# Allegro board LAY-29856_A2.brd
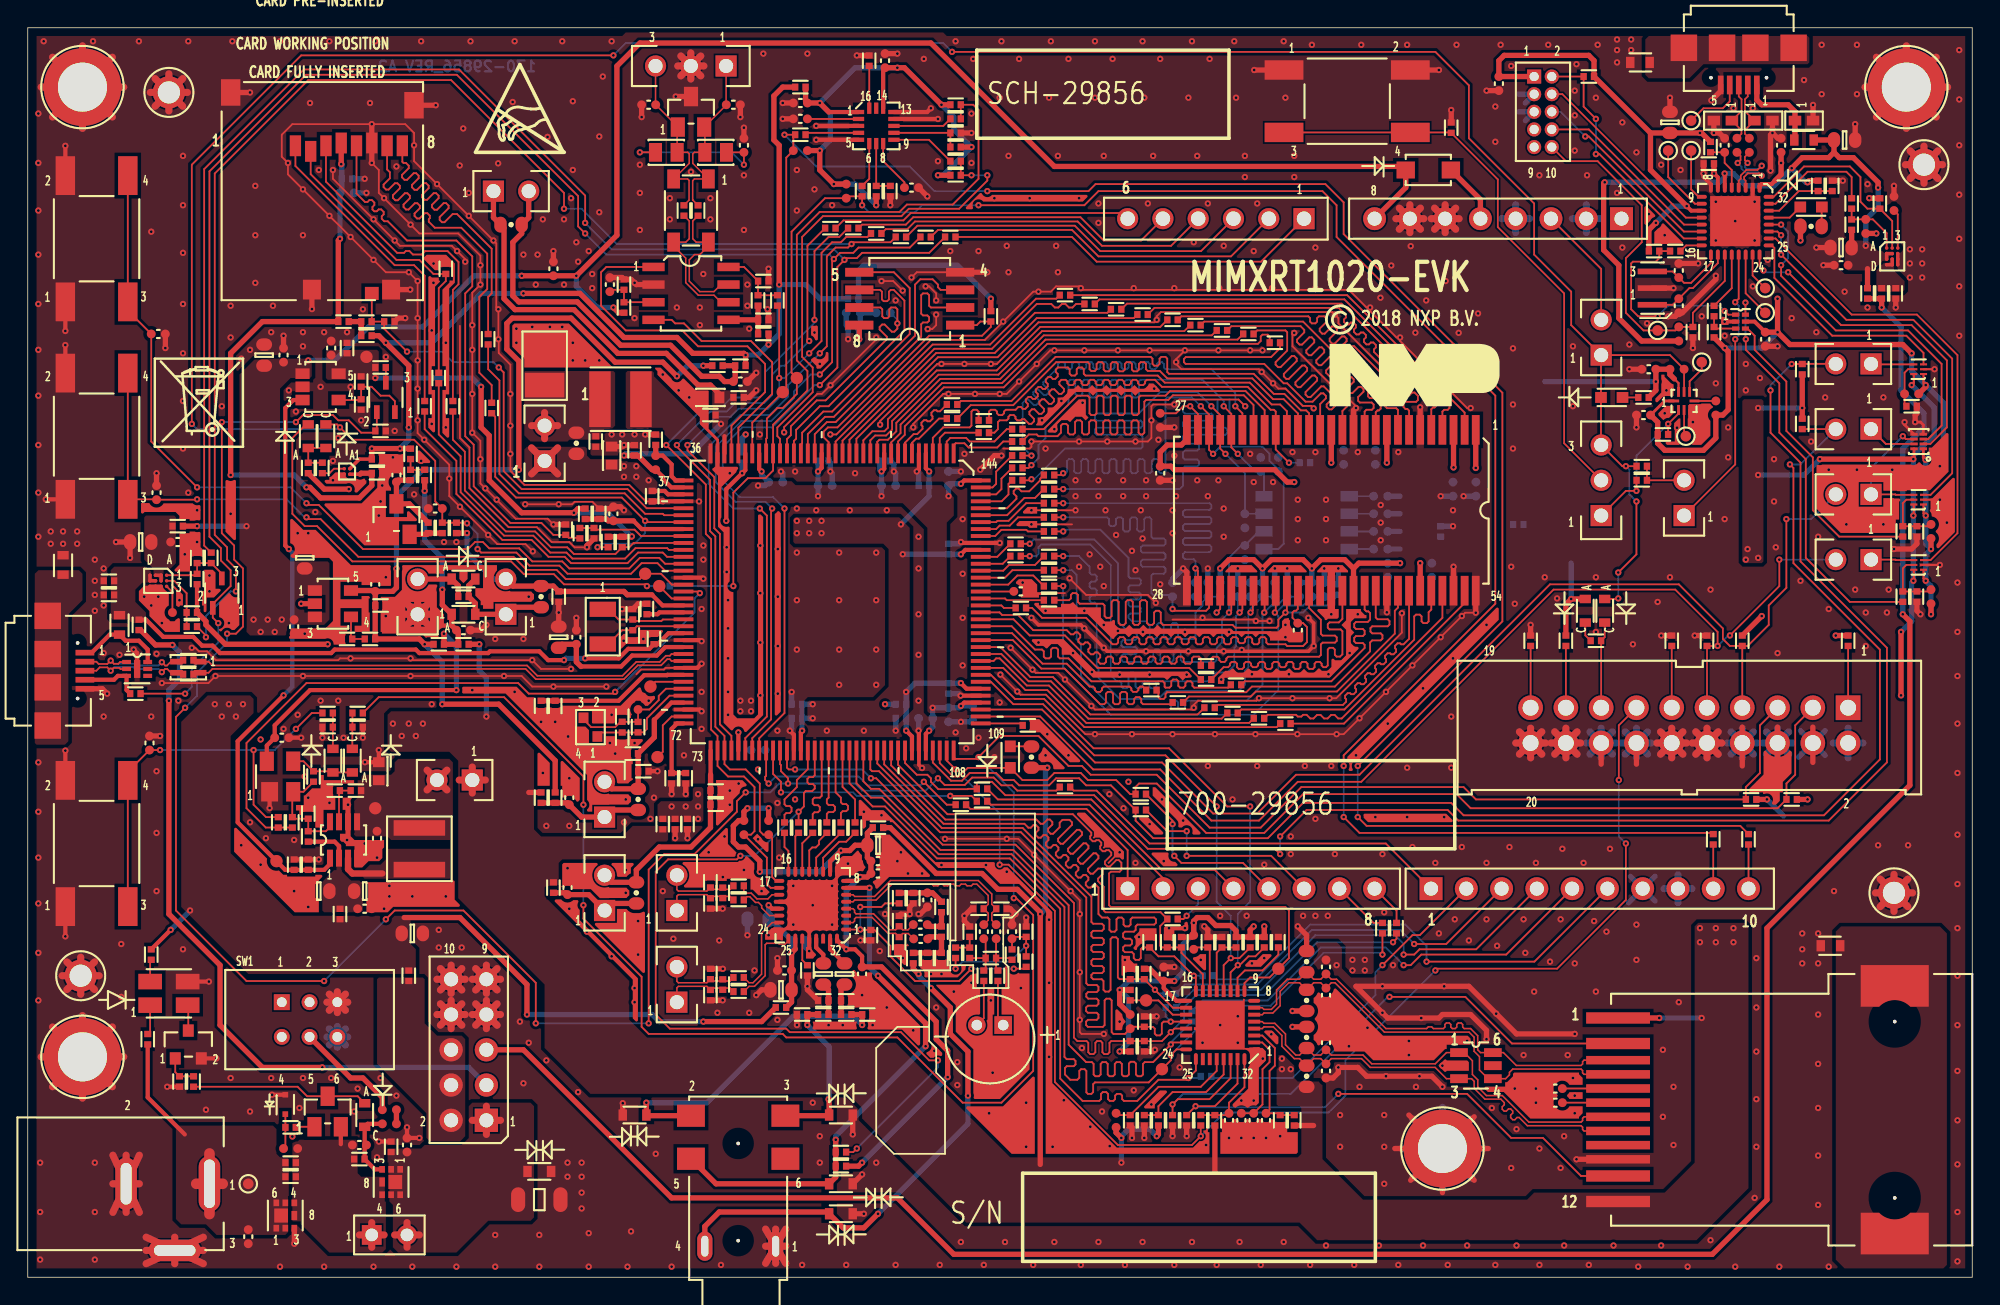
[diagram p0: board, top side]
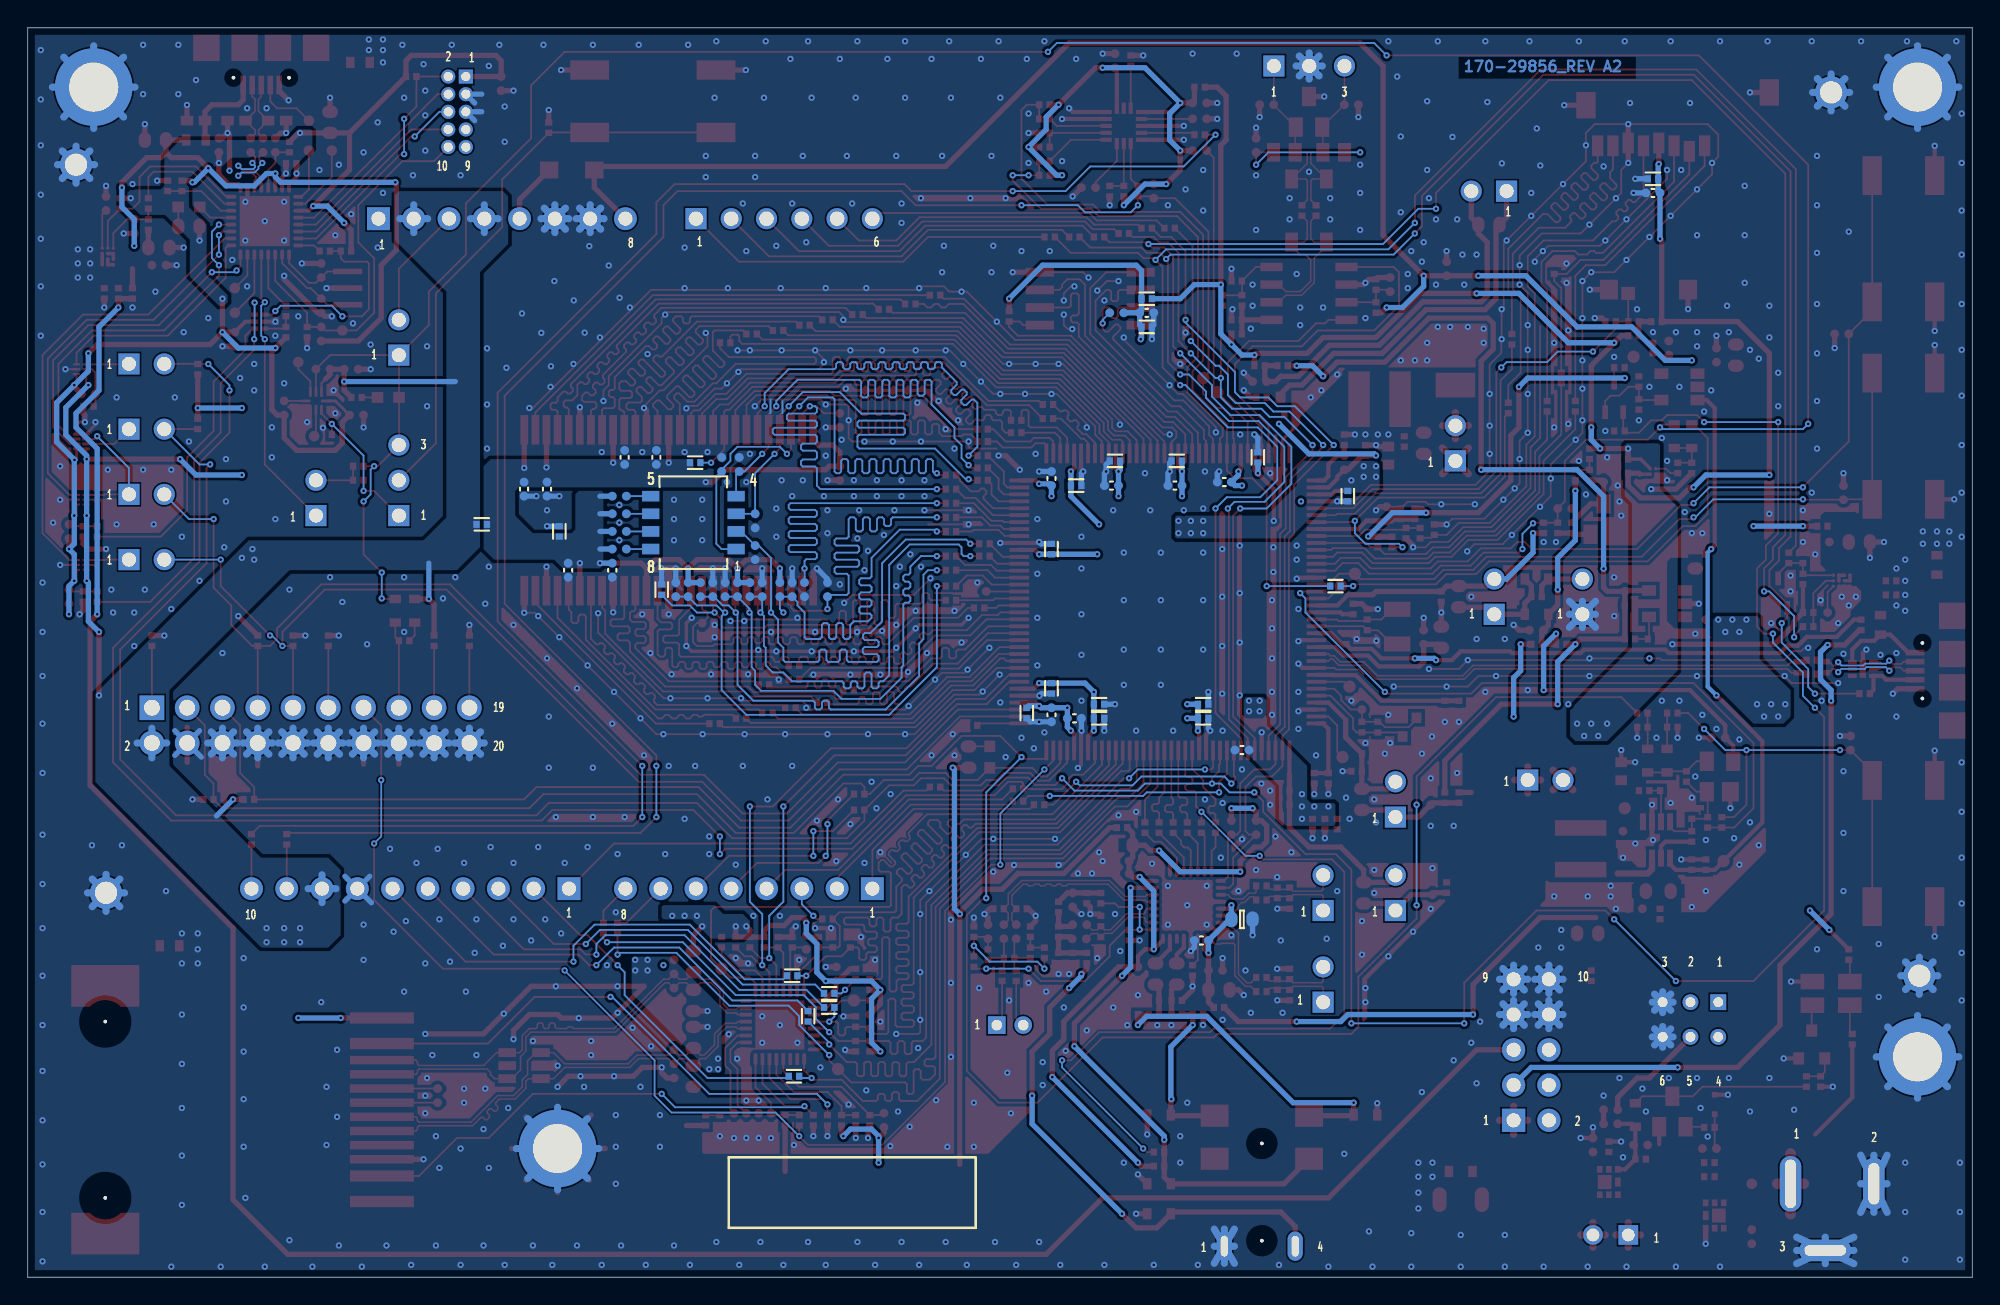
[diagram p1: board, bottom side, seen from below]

Outline 140 x 90 mm; copper layers: TOP, BOTTOM. Coordinates in mm from the lower left corner of the outline.
Outline path: 0,90 140,90 140,0 0,0 0,90

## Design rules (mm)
net group AUD_INT: nets AUD_INT N99827729
net group CAN1_H: nets CAN1_H N101254622
net group CAN1_L: nets CAN1_L N101254624
net group DP_SDA_USB_D: nets SDA_USB_DN SDA_USB_DP
net group ENET_RST: nets ENET_RST N101050998
net group ENET_RX: nets ENET_RXM ENET_RXP
net group ENET_TX: nets ENET_TXM ENET_TXP
net group GPIO_AD_B0_07: nets GPIO_AD_B0_07 N101505087
net group GPIO_AD_B1_08: nets GPIO_AD_B1_08 N101505089
net group GPIO_AD_B1_09: nets GPIO_AD_B1_09 N101505091
net group GPIO_AD_B1_11: nets GPIO_AD_B1_11 N100784828
net group GPIO_EMC_16: nets GPIO_EMC_16 SEMC_A0
net group GPIO_EMC_17: nets GPIO_EMC_17 SEMC_A1
net group GPIO_EMC_18: nets GPIO_EMC_18 SEMC_A2
net group GPIO_EMC_19: nets GPIO_EMC_19 SEMC_A3
net group GPIO_EMC_20: nets GPIO_EMC_20 SEMC_A4
net group GPIO_EMC_21: nets GPIO_EMC_21 SEMC_A5
net group GPIO_EMC_22: nets GPIO_EMC_22 SEMC_A6
net group GPIO_EMC_23: nets GPIO_EMC_23 SEMC_A7
net group GPIO_EMC_24: nets GPIO_EMC_24 SEMC_A8
net group GPIO_EMC_25: nets GPIO_EMC_25 SEMC_A9
net group GPIO_EMC_26: nets GPIO_EMC_26 SEMC_A11
net group GPIO_EMC_27: nets GPIO_EMC_27 SEMC_A12
net group HP_MIC1: nets HP_MIC1N HP_MIC1P
net group MAIN_MIC2: nets MAIN_MIC2N MAIN_MIC2P
net group N99903738: nets N99903738 N99904961
net group OTG1_DN: nets N99833038 OTG1_DN
net group OTG1_DP: nets N99833040 OTG1_DP
net group SAI1_MCLK: nets N99827829 SAI1_MCLK
net group SAI1_RXD: nets N99827789 SAI1_RXD
net group SAI1_TX_BCLK: nets N99827769 SAI1_TX_BCLK
net group SAI1_TX_SYNC: nets N99827749 SAI1_TX_SYNC
net group SAI1_TXD: nets N99827809 SAI1_TXD
net group SD1_CLK: nets N100763759 SD1_CLK
net group SD1_CMD: nets N100585038 SD1_CMD
net group SD1_D0: nets N100585007 SD1_D0
net group SD1_D1: nets N100585009 SD1_D1
net group SD1_D2: nets N100585016 SD1_D2
net group SD1_D3: nets N100585089 SD1_D3
net group SDA_USB: nets SDA_USB_CONN_DN SDA_USB_CONN_DP
net group SEMC_A10: nets N101509422 SEMC_A10
net group SEMC_BA0: nets N101509590 SEMC_BA0
net group SEMC_BA1: nets N101509597 SEMC_BA1
net group SEMC_CAS: nets N101510168 SEMC_CAS
net group SEMC_CKE: nets N101509855 SEMC_CKE
net group SEMC_CLK: nets N101219622 SEMC_CLK
net group SEMC_CS0: nets N101511316 SEMC_CS0
net group SEMC_D0: nets N101507443 SEMC_D0
net group SEMC_D1: nets N101507450 SEMC_D1
net group SEMC_D2: nets N101507457 SEMC_D2
net group SEMC_D3: nets N101507470 SEMC_D3
net group SEMC_D4: nets N101507472 SEMC_D4
net group SEMC_D5: nets N101507474 SEMC_D5
net group SEMC_D6: nets N101507491 SEMC_D6
net group SEMC_D7: nets N101507493 SEMC_D7
net group SEMC_D8: nets N101507495 SEMC_D8
net group SEMC_D9: nets N101507512 SEMC_D9
net group SEMC_D10: nets N101507514 SEMC_D10
net group SEMC_D11: nets N101507516 SEMC_D11
net group SEMC_D12: nets N101507533 SEMC_D12
net group SEMC_D13: nets N101507535 SEMC_D13
net group SEMC_D14: nets N101507537 SEMC_D14
net group SEMC_D15: nets N101507548 SEMC_D15
net group SEMC_DM0: nets N101509859 SEMC_DM0
net group SEMC_DM1: nets N101509857 SEMC_DM1
net group SEMC_RAS: nets N101509861 SEMC_RAS
net group SEMC_WE: nets N101509863 SEMC_WE
net group SPK_LN: nets N99828318 SPK_LN
net group SPK_LP: nets N99828322 SPK_LP
net group SPK_RN: nets N99827958 SPK_RN
net group SPK_RP: nets N99827962 SPK_RP
net group 3W: nets JTAG_DACK JTAG_NSRST JTAG_RTCK JTAG_TCK N99881896 SDA_JTAG_TCLK SDA_RST SDA_RST_LED SDA_RST_TGTMCU_B SDA_RST_TGTMCU_J_B SDA_SPI0_RST_B SDA_SPI0_SCK SW1_RST_B SWD_CLK_TGTMCU_BUF
net group ENET_RXD1: nets N101505079
net group GPIO_AD_B1_10: nets GPIO_AD_B1_10 N100784802 N101140611
net group POWER: nets 5V_USB_OTG CAN_VIO_3V3 DCDC_3V3_PG FLASH_3V3 HP_JD MCU_DCDC_IN N99781517 N99781633 N99781637 N99833017 N99833020 N99903207 N99903209 N99903219 N99903223 N99904959 N99904975 N99916957 N100054253 N100054299 P5V0_SDA_USB_CONN_VBUS P5V_SDA_S SENSOR_3V3 VAUD_3V3 VDD_COIN_3V VDD_HIGH_IN_3V3 VDD_HIGH_IN_MCU VDD_SNVS_3V3 VDD_SNVS_IN VDD_USB_3V VDDA_ADC_3P3_MCU VDDA_ADC_3V3 VLDO_3V3 VSD_3V3
net group SD1: nets SD_CD_SW

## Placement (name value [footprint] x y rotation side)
C1  0.1UF  [CC0402_25]  27.3 9.53 90 top
C2  1.0UF  [0402_CC]  26.16 9.4 90 top
C3  47uF  [CC1206_OV]  36.83 5.59 0 top
C4  0.1UF  [CC0402_25]  15.88 2.92 270 top
C5  0.01UF  [CC0402_25]  23.88 9.53 0 top
C6  1.0UF  [0402_CC]  49.53 35.05 0 top
C7  0.22uF  [0402_CC]  49.53 34.04 0 top
C8  0.22uF  [0402_CC]  64.52 57.02 180 bottom
C9  0.22uF  [0402_CC]  66.29 52.45 90 bottom
C10  0.22uF  [0402_CC]  51.44 59.05 90 bottom
C11  0.22uF  [0402_CC]  44.96 56.26 270 bottom
C12  0.22uF  [0402_CC]  66.29 42.42 270 bottom
C13  0.22uF  [0402_CC]  62.87 40.26 180 bottom
C14  0.22uF  [0402_CC]  62.87 41.27 180 bottom
C15  0.22uF  [0402_CC]  55.37 40.26 180 bottom
C16  0.22uF  [0402_CC]  55.37 41.27 180 bottom
C17  4.7uF  [0402_CC]  44.96 56.26 270 top
C18  22UF  [0603_CC]  42.04 59.18 90 top
C19  4.7uF  [0402_CC]  44.32 36.45 0 top
C20  0.22uF  [0402_CC]  43.56 37.72 180 top
C21  4.7uF  [0402_CC]  37.97 41.15 270 top
C22  0.22uF  [0402_CC]  36.96 41.15 270 top
C23  0.22uF  [0402_CC]  38.23 49.02 270 top
C24  0.22uF  [0402_CC]  44.58 48.13 90 top
C25  0.22uF  [0402_CC]  47.37 35.94 270 top
C26  4.7uF  [0402_CC]  46.35 35.94 270 top
C28  0.1UF  [CC0402_25]  29.34 55.37 180 top
C29  0.1UF  [CC0402_25]  26.54 57.78 90 top
C30  1.0UF  [0402_CC]  25.15 57.91 0 top
C31  22UF  [0603_CC]  49.15 63.37 180 top
C32  4.7uF  [0402_CC]  51.18 63.37 0 top
C33  0.22uF  [0402_CC]  49.15 62.1 180 top
C35  0.22uF  [0402_CC]  43.69 59.56 90 top
C36  4.7PF  [0402_CC]  42.8 40.39 90 top
C37  4.7PF  [0402_CC]  42.8 38.86 270 top
C38  33UF  [CC1210]  37.21 65.66 90 top
C39  0.22uF  [0402_CC]  40.89 60.2 270 top
C40  10uF  [CC0603_OV]  19.94 51.82 90 top
C41  0.1UF  [CC0402_25]  19.18 46.86 270 top
C42  4.7uF  [0402_CC]  25.4 48.39 0 top
C43  0.1UF  [CC0402_25]  25.02 49.91 90 top
C44  18PF  [0402_CC]  43.56 47.75 90 top
C45  18PF  [0402_CC]  43.56 46.23 270 top
C46  0.22uF  [0402_CC]  45.21 60.33 90 top
C47  0.1UF  [CC0402_25]  38.86 28.07 90 top
C48  0.1UF  [CC0402_25]  31.37 46.61 0 top
C49  10uF  [CC0603_OV]  20.95 27.81 180 top
C50  10uF  [CC0603_OV]  24.26 27.81 0 top
C51  0.1UF  [CC0402_25]  24.26 26.54 0 top
C52  22UF  [0603_CC]  25.27 36.45 90 top
C53  0.1UF  [CC0402_25]  25.15 31.62 270 top
C54  0.22uF  [0402_CC]  20.19 33.4 90 top
C55  0.1UF  [CC0402_25]  51.31 64.52 0 top
C56  0.1UF  [CC0402_25]  38.99 34.54 90 top
C57  1000pF  [0402_CC]  20.19 29.72 90 top
C58  1000pF  [0402_CC]  19.18 29.72 90 top
C59  1000pF  [0402_CC]  21.59 39.62 180 top
C60  0.1UF  [CC0402_25]  18.29 38.86 0 top
C61  1.0UF  [0402_CC]  23.75 40.64 180 top
C62  10uF  [CC0603_OV]  17.02 66.42 90 top
C63  0.1UF  [CC0402_25]  18.41 66.42 90 top
C64  4.7uF  [0402_CC]  22.99 66.93 90 top
C65  0.1UF  [CC0402_25]  21.84 66.93 90 top
C66  4.7uF  [0402_CC]  47.5 32.64 270 top
C67  0.1UF  [CC0402_25]  64.64 40.26 180 bottom
C68  0.1UF  [CC0402_25]  52.58 37.97 0 bottom
C69  0.1UF  [CC0402_25]  57.4 57.02 0 bottom
C70  0.1UF  [CC0402_25]  66.29 57.53 90 bottom
C71  4.7uF  [0402_CC]  46.61 32.64 270 top
C72  0.1UF  [CC0402_25]  61.98 57.02 0 bottom
C73  0.1UF  [CC0402_25]  53.85 57.28 0 bottom
C74  0.1UF  [CC0402_25]  66.29 40.51 270 bottom
C75  0.1UF  [CC0402_25]  71.5 49.4 0 top
C76  4.7uF  [0402_CC]  41.15 54.99 90 top
C77  0.1UF  [CC0402_25]  42.16 54.99 90 top
C78  1.0UF  [0402_CC]  45.09 45.97 90 top
C79  10uF  [CC0603_OV]  38.23 46.1 90 top
C80  0.1UF  [CC0402_25]  39.5 46.1 90 top
C81  4.7uF  [0402_CC]  5.84 49.15 180 top
C82  10uF  [CC0603_OV]  8.13 52.96 180 top
C83  0.1UF  [CC0402_25]  10.79 52.96 0 top
C84  4.7uF  [0402_CC]  5.84 50.16 180 top
C85  0.1UF  [CC0402_25]  41.91 71.5 90 top
C86  1.0UF  [0402_CC]  42.93 71.5 90 top
C87  1.0UF  [0402_CC]  52.96 68.96 0 top
C88  56PF  [CC0402_25]  50.8 84.45 180 top
C89  0.01UF  [CC0402_25]  51.56 81.53 90 top
C90  56PF  [CC0402_25]  44.7 84.45 180 top
C91  10uF  [CC0603_OV]  61.21 31.11 0 top
C92  0.1UF  [CC0402_25]  61.21 29.08 0 top
C93  0.1UF  [CC0402_25]  60.07 21.84 270 top
C94  0.1UF  [CC0402_25]  61.21 29.97 0 top
C95  10uF  [CC0603_OV]  54.23 20.7 180 top
C96  0.1UF  [CC0402_25]  54.48 22.1 180 top
C97  0.1UF  [CC0402_25]  55.5 24.26 0 bottom
C98  4.7uF  [0402_CC]  60.71 24.64 270 top
C99  10uF  [CC0603_OV]  52.58 25.78 180 bottom
C100  4.7uF  [0402_CC]  56.13 22.1 270 top
C101  220PF  [0402_CC]  60.45 18.92 180 top
C102  22UF  [CC0603_OV]  58.8 21.84 270 top
C103  22UF  [CC0603_OV]  57.28 21.84 270 top
C104  220PF  [0402_CC]  55.75 18.92 180 top
C105  4.7uF  [0402_CC]  71.88 24.89 90 top
C106  0.1UF  [CC0402_25]  70.87 24.89 90 top
C107  15PF  [0402_CC]  70.1 26.54 180 top
C108  4.7uF  [0402_CC]  63.75 27.3 270 top
C109  0.1UF  [CC0402_25]  64.77 27.18 270 top
C110  15PF  [0402_CC]  62.74 25.65 270 top
C111  0.1UF  [CC0402_25]  69.72 24.89 90 top
C112  0.1UF  [CC0402_25]  64.26 25.4 0 top
C113  4.7uF  [0402_CC]  66.8 23.37 90 top
C114  0.1UF  [CC0402_25]  68.83 24.89 90 top
C115  0.1UF  [CC0402_25]  64.29 24.37 0 top
C116  15PF  [0402_CC]  62.74 24.13 270 top
C117  15PF  [0402_CC]  64.77 22.99 270 top
C118  15PF  [0402_CC]  65.79 22.99 270 top
C119  15PF  [0402_CC]  68.45 26.54 180 top
C120  15PF  [0402_CC]  49.15 28.45 270 top
C121  15PF  [0402_CC]  49.15 21.84 270 top
C122  15PF  [0402_CC]  50.04 27.69 270 top
C123  15PF  [0402_CC]  50.04 21.08 270 top
C124  15PF  [0402_CC]  49.15 26.92 270 top
C125  15PF  [0402_CC]  49.15 20.32 270 top
C126  4.7uF  [0402_CC]  90.17 11.3 270 top
C127  0.1UF  [CC0402_25]  89.15 11.3 270 top
C128  2.2uF  [CC0402_25]  87.38 11.3 270 top
C129  0.1UF  [CC0402_25]  88.27 11.3 270 top
C130  10PF  [CC0402_25]  93.47 22.35 90 top
C131  10PF  [CC0402_25]  93.47 20.32 270 top
C132  10PF  [CC0402_25]  93.47 16.89 90 top
C133  10PF  [CC0402_25]  93.47 14.86 270 top
C134  0.1UF  [CC0402_25]  81.79 21.84 90 top
C135  0.1UF  [CC0402_25]  109.98 12.57 180 top
C136  0.1UF  [CC0402_25]  109.98 13.59 180 top
C137  0.1UF  [CC0402_25]  86.49 11.3 270 top
C138  4.7uF  [0402_CC]  22.99 79.12 0 bottom
C139  0.1UF  [CC0402_25]  22.99 78.11 0 bottom
C140  18PF  [0402_CC]  40.77 53.59 270 top
C141  18PF  [0402_CC]  38.73 53.85 90 top
C142  1.0UF  [0402_CC]  59.44 68.45 180 bottom
C143  0.1UF  [CC0402_25]  59.44 69.47 180 bottom
C144  4.7uF  [0402_CC]  101.73 53.72 90 bottom
C145  0.1UF  [CC0402_25]  102.62 56.77 270 bottom
C146  0.1UF  [CC0402_25]  104.27 56.77 270 bottom
C147  0.1UF  [CC0402_25]  97.92 50.93 270 bottom
C148  0.1UF  [CC0402_25]  97.03 59.05 90 bottom
C149  0.1UF  [CC0402_25]  81.53 57.91 270 top
C150  0.1UF  [CC0402_25]  101.09 50.93 270 bottom
C151  0.1UF  [CC0402_25]  94.74 59.05 90 bottom
C152  0.1UF  [CC0402_25]  116.71 65.41 180 top
C153  0.1UF  [CC0402_25]  116.33 62.1 180 top
C154  0.1UF  [CC0402_25]  125.09 67.56 270 top
C155  10uF  [CC0603_OV]  118.24 83.19 90 top
C156  1.0UF  [0402_CC]  121.03 80.21 180 top
C157  0.1UF  [CC0402_25]  126.24 81.53 90 top
C158  1000pF  [0402_CC]  102.49 82.8 90 top
C159  10uF  [CC0603_OV]  130.81 81.92 0 top
C160  22PF  [CC0402_25]  118.87 69.98 270 top
C161  22PF  [CC0402_25]  118.87 72.52 90 top
C162  2.2uF  [CC0402_25]  122.17 81.53 90 top
C163  0.1UF  [CC0402_25]  105.92 85.98 270 top
C164  10uF  [CC0603_OV]  130.56 74.17 180 top
C165  0.1UF  [CC0402_25]  130.56 72.9 180 top
C166  4.7uF  [0402_CC]  134.49 70.87 270 top
C167  0.1UF  [CC0402_25]  61.72 87.63 90 top
C168  0.1UF  [CC0402_25]  55.63 84.58 180 top
C169  0.1UF  [CC0402_25]  63.63 78.49 0 top
C170  0.1UF  [CC0402_25]  55.63 83.44 180 top
C171  1.0UF  [0402_CC]  25.15 58.93 0 top
C172  0.1UF  [CC0402_25]  9.4 67.94 0 top
C173  0.1UF  [CC0402_25]  8.76 38.48 90 top
C174  0.1UF  [CC0402_25]  9.27 56.52 90 top
C175  10PF  [CC0402_25]  91.44 46.61 270 top
C176  4.7uF  [0402_CC]  68.07 40.64 270 bottom
C177  4.7uF  [0402_CC]  61.72 58.8 0 bottom
C178  4.7uF  [0402_CC]  57.28 58.8 0 bottom
C179  10uF  [CC0603_OV]  27.69 24.77 0 top
C180  0.1UF  [CC0402_25]  37.85 72.64 90 top
D1  MM5Z5V1ST1G  [SOD_523_1P4]  18.54 12.45 90 top
D2  RB521S30  [SOD523]  24.26 11.68 90 top
D3  LED_RED-GRN  [LED_DUAL_3025MM_SM]  10.16 20.45 0 top
D4  RB521S30  [SOD523]  31.37 47.75 180 top
D5  GREEN  [LED_0603]  70.74 37.47 270 top
D6  RB521S30  [SOD523]  31.37 50.29 180 top
D7  RB521S30  [SOD523]  20.19 60.58 270 top
D8  RB521S30  [SOD523]  21.46 60.58 270 top
D9  RB521S30  [SOD523]  21.97 37.21 270 top
D10  RB521S30  [SOD523]  23.37 37.21 270 top
D11  NUP2105L  [SOT-23]  47.75 83.95 0 top
D12  RB521S30  [SOD523]  112.14 48.01 90 top
D13  RB521S30  [SOD523]  113.54 48.01 90 top
D14  MBR120VLSFT1G  [SOD-123]  100.84 79.76 0 top
D15  RED  [LED_0603]  114.05 63.37 180 top
D16  GREEN  [LED_0603]  128.4 77.09 180 top
FL1  ACT45B-510-2P  [IND4_4P7X3P4_SMT]  47.75 76.83 270 top
H1  .635" LONG  [SPACER_139T]  3.94 85.72 0 top
H2  .635" LONG  [SPACER_139T]  135.25 85.72 0 top
H3  .635" LONG  [SPACER_139T]  3.94 15.88 0 top
H4  .635" LONG  [SPACER_139T]  101.85 9.27 270 top
J1  HDR 2X5  [HDR205]  33.02 11.3 180 top
J2  CON_1_PWR  [CON3_PWR_TH]  13.08 6.73 270 top
J3  HDR 1X2  [HDR102]  41.53 26.42 180 top
J4  HDR 1X2  [HDR102]  37.21 58.8 180 top
J5  HDR 1X2  [HDR102]  41.53 33.15 180 top
J6  HDR 1X2  [HDR102]  34.42 47.75 180 top
J7  HDR 1X2  [HDR102]  28.07 47.75 180 top
J8  HDR 1X2  [HDR102]  32 35.81 270 top
J9  USB_MICROAB_RECEPTACLE  [CON_USB5_MICROAB_0P65_SM]  1.47 43.69 270 top
J10  HDR_1X3  [HDR103]  50.28 87.25 270 top
J11  PJ31360-I  [CON6_AUDJACK_RA_TH]  53.85 2.24 90 top
J12  HDR 1X2  [HDR102]  46.74 26.42 180 top
J13  HDR 1X2  [HDR102]  46.74 19.81 180 top
J14  RJ45_YLW+GRN  [CON12_RJ45_1P02_SM]  124.46 12.06 270 top
J15  95220030-14RRF  [CON_SDCARD_95220]  21.21 78.23 0 top
J16  BH25420B301  [HDR_2X10M_100_TH]  131.06 41.02 270 top
J17  CON 1X8  [CON_SKT1X8_TH]  79.19 27.99 90 top
J18  CON 1X6  [CON_SKT1X6_TH]  91.89 76.25 270 top
J19  CON 1X10  [CON_SKT1X10_TH]  101.03 27.99 90 top
J20  CON 1X8  [CON_SKT1X8_TH]  114.75 76.25 270 top
J21  HDR 1X2  [HDR102]  113.28 66.42 180 top
J22  HDR_1X3  [HDR103]  113.28 54.86 180 top
J23  USB_MICROAB_RECEPTACLE  [CON_USB5_MICROAB_0P65_SM]  123.19 88.52 180 top
J24  HDR 1X2  [HDR102]  119.25 54.86 180 top
J25  HDR 1X2  [HDR102]  132.72 65.79 270 top
J26  HDR 1X2  [HDR102]  132.72 61.09 270 top
J27  HDR 1X2  [HDR102]  132.72 56.39 270 top
J28  HDR 1X2  [HDR102]  132.72 51.69 270 top
J29  HDR 2X5  [HDR205_50_TH]  108.46 86.49 270 top
J37  HDR 1X2  [HDR102]  33.53 78.23 90 top
JP1  SHORT_100mil  [100MIL_TH]  24.77 3.05 0 top
L1  4.7uH  [IND_VLS4012E]  42.67 63.25 0 top
L2  1uH  [IND_4020]  28.19 30.86 90 top
L3  330 OHM  [IND_1608]  6.6 46.99 90 top
L4  90OHM  [IND4_CHOKE_0805]  11.56 43.94 180 top
L5  330 OHM  [IND_1608]  2.54 51.31 90 top
L6  120 Ohm  [0402_CC]  58.93 18.92 0 top
L7  120 Ohm  [0402_CC]  57.28 18.92 180 top
L8  120 Ohm  [0402_CC]  63.75 22.99 270 top
L9  120 Ohm  [0402_CC]  91.19 11.3 90 top
L10  330 OHM  [IND_1608]  129.79 23.88 0 top
L11  330 OHM  [IND_1608]  127.89 81.92 0 top
L12  330 OHM  [IND_1608]  116.08 87.5 180 top
L13  120 Ohm  [0402_CC]  107.31 54.23 180 bottom
L20  120 Ohm  [0402_CC]  27.43 21.72 90 top
NOREF  -  []  4.36 39.91 90 top
NOREF#2  -  []  121.19 86.4 0 top
NOREF#3  -  []  14.13 70.56 90 top
NOREF#4  -  []  134.64 72.93 90 top
NOREF#5  -  []  1.44 39.74 90 top
NOREF#6  -  []  114.5 5.45 90 top
NOREF#7  -  []  8.56 49.48 0 top
NOREF#8  -  []  135.62 50.78 90 top
NOREF#9  -  []  119.45 62.5 90 top
NOREF#10  -  []  59.87 72.39 0 top
NOREF#11  -  []  138.11 80.14 0 top
NOREF#12  -  []  22.59 57.64 90 top
NOREF#13  -  []  26.16 71.14 90 top
NOREF#14  -  []  59.87 71.12 90 top
NOREF#15  -  []  22.59 57.64 0 top
NOREF#16  -  []  59.81 81.93 0 top
NOREF#17  -  []  8.8 49.76 0 top
NOREF#18  -  []  0 0 0 top
NOREF#19  -  []  118.85 62.47 0 top
NOREF#20  -  []  118.53 62.49 0 top
NOREF#21  -  []  8.56 49.48 90 top
NOREF#22  -  []  119.42 85.63 90 top
NOREF#23  -  []  22.57 81.7 90 top
NOREF#24  -  []  -0.57 11.33 90 top
NOREF#25  -  []  0 0 90 top
NOREF#26  -  []  121.89 85.88 0 top
NOREF#27  -  []  62.36 81.93 90 top
NOREF#28  -  []  121.89 85.88 0 top
NOREF#29  -  []  4.11 42.39 90 top
NOREF#30  -  []  10.58 1.93 0 top
NOREF#31  -  []  14.61 85.34 0 top
NOREF#32  -  []  -0.01 39.2 90 top
NOREF#33  -  []  22.79 57.84 0 top
NOREF#34  -  []  139.82 2.47 90 top
NOREF#35  -  []  -0.79 39.91 90 top
NOREF#36  -  []  135.79 65.76 0 top
NOREF#37  -  []  60.59 81.66 90 top
NOREF#38  -  []  108.2 38.48 90 top
NOREF#39  -  []  44.34 61.19 90 top
NOREF#40  -  []  20.46 71.14 90 top
NOREF#41  -  []  62.57 84.43 0 top
NOREF#42  -  []  108.46 86.49 0 top
NOREF#43  -  []  47.75 11.64 0 top
NOREF#44  -  []  47.8 12.84 0 top
NOREF#45  -  []  114.5 15.63 90 top
NOREF#46  -  []  9.14 59.82 0 top
NOREF#47  -  []  94.49 68.96 0 top
NOREF#48  -  []  47.91 38.64 90 top
NOREF#49  -  []  32.26 81.03 0 top
NOREF#50  -  []  82.04 30.86 0 top
NOREF#51  -  []  114.5 8.5 90 top
NOREF#52  -  []  114.04 24.47 0 top
NOREF#53  -  []  108.46 85.22 90 top
NOREF#54  -  []  3.59 41.69 90 top
NOREF#55  -  []  60.77 67.74 90 top
NOREF#56  -  []  41.01 38.95 90 top
NOREF#57  -  []  135.79 51.66 0 top
NOREF#58  -  []  7.08 6.73 90 top
NOREF#59  -  []  21.47 81.5 0 top
NOREF#60  -  []  135.62 55.48 90 top
NOREF#61  -  []  122.96 68.33 0 top
NOREF#62  -  []  5.4 21.72 0 top
NOREF#63  -  []  -0.79 39.91 0 top
NOREF#64  -  []  47.8 -0.01 90 top
NOREF#65  -  []  60.78 73.24 0 top
NOREF#66  -  []  119.65 62.47 90 top
NOREF#67  -  []  114.5 5.45 90 top
NOREF#68  -  []  14.13 70.56 0 top
NOREF#69  -  []  71.63 1.14 0 top
NOREF#70  -  []  59.87 72.39 0 top
NOREF#71  -  []  1.44 39.74 90 top
NOREF#72  -  []  41.36 38.57 90 top
NOREF#73  -  []  135.79 56.36 0 top
NOREF#74  -  []  119.24 88.55 0 top
NOREF#75  -  []  114.18 3.89 90 top
NOREF#76  -  []  47.91 38.64 0 top
NOREF#77  -  []  139.82 2.47 90 top
NOREF#78  -  []  133.84 72.93 0 top
NOREF#79  -  []  20.46 71.14 90 top
NOREF#80  -  []  110.74 41.02 0 top
NOREF#81  -  []  134.42 3.15 90 top
NOREF#82  -  []  40.62 61.58 0 top
NOREF#83  -  []  114.5 5.45 90 top
NOREF#84  -  []  114.5 7.29 90 top
NOREF#85  -  []  51.15 2.64 90 top
NOREF#86  -  []  135.62 51.83 0 top
NOREF#87  -  []  47.8 -0.01 0 top
NOREF#88  -  []  20.46 71.14 90 top
NOREF#89  -  []  93.73 62.74 0 top
NOREF#90  -  []  59.87 68.58 90 top
NOREF#91  -  []  14.61 85.34 0 top
NOREF#92  -  []  4.11 42.39 90 top
NOREF#93  -  []  49.16 37.94 90 top
NOREF#94  -  []  8.8 49.76 0 top
NOREF#95  -  []  60.59 81.66 0 top
NOREF#96  -  []  59.87 71.12 90 top
NOREF#97  -  []  62.36 81.93 90 top
NOREF#98  -  []  133.55 72.69 0 top
NOREF#99  -  []  60.77 67.74 90 top
NOREF#100  -  []  103.12 44.23 0 top
NOREF#101  -  []  13.08 6.73 90 top
NOREF#102  -  []  53.85 2.24 90 top
NOREF#103  -  []  135.62 64.88 90 top
NOREF#104  -  []  119.42 85.63 90 top
NOREF#105  -  []  47.21 57.39 0 top
NOREF#106  -  []  103.12 34.96 90 top
NOREF#107  -  []  1.44 42.49 90 top
NOREF#108  -  []  60.78 73.24 0 top
NOREF#109  -  []  47.75 8.54 0 top
NOREF#110  -  []  14.61 85.34 0 top
NOREF#111  -  []  135.62 56.53 0 top
NOREF#112  -  []  62.36 81.93 90 top
NOREF#113  -  []  61.59 81.66 90 top
NOREF#114  -  []  28.28 70.56 90 top
NOREF#115  -  []  22.79 57.84 0 top
NOREF#116  -  []  47.21 52.89 90 top
NOREF#117  -  []  0 0.03 0 top
NOREF#118  -  []  135.95 27.69 0 top
NOREF#119  -  []  62.59 81.43 90 top
NOREF#120  -  []  8.8 49.76 90 top
NOREF#121  -  []  68.33 82.04 0 top
NOREF#122  -  []  135.79 51.31 90 top
NOREF#123  -  []  10.58 1.93 90 top
NOREF#124  -  []  133.84 72.93 0 top
NOREF#125  -  []  41.2 63.25 0 top
NOREF#126  -  []  47.8 -0.01 0 top
NOREF#127  -  []  20.46 71.14 90 top
NOREF#128  -  []  107.32 87.31 0 top
NOREF#129  -  []  48.75 2.24 90 top
NOREF#130  -  []  14.13 85.91 0 top
NOREF#131  -  []  14.61 85.34 0 top
NOREF#132  -  []  24.77 70.86 90 top
NOREF#133  -  []  134.64 72.93 90 top
NOREF#134  -  []  134.42 5.71 90 top
NOREF#135  -  []  107.32 80.58 90 top
NOREF#136  -  []  114.5 16.84 90 top
NOREF#137  -  []  -0.57 11.33 0 top
NOREF#138  -  []  14.61 85.34 0 top
NOREF#139  -  []  47.75 11.64 0 top
NOREF#140  -  []  8.8 50.16 90 top
NOREF#141  -  []  59.87 68.58 90 top
NOREF#142  -  []  134.93 72.69 90 top
NOREF#143  -  []  47.8 -0.01 0 top
NOREF#144  -  []  135.79 65.41 90 top
NOREF#145  -  []  108.46 81.41 90 top
NOREF#146  -  []  121.99 88.55 0 top
NOREF#147  -  []  119.42 90.78 0 top
NOREF#148  -  []  119.24 88.55 90 top
NOREF#149  -  []  59.59 81.43 0 top
NOREF#150  -  []  39.66 40.67 0 top
NOREF#151  -  []  135.79 56.01 90 top
NOREF#152  -  []  108.2 41.02 0 top
NOREF#153  -  []  14.13 70.56 90 top
NOREF#154  -  []  40.01 40.3 0 top
NOREF#155  -  []  121.19 86.4 90 top
NOREF#156  -  []  11.75 85.34 0 top
NOREF#157  -  []  135.62 65.93 0 top
NOREF#158  -  []  89.53 3.56 180 bottom
P1  EM6022P  [MIC_WM-63PR]  70.23 18.16 90 top
Q1  FDMA530PZ  [MLP6_2X2MM_SLUG]  18.54 4.45 90 top
Q2  FDMA530PZ  [MLP6_2X2MM_SLUG]  26.16 6.86 270 top
Q3  BC807-40  [SOT-23]  21.59 11.94 0 top
Q4  BSH111BK  [SOT23_A]  11.56 16.76 0 top
Q8  2SK3018  [SOT323_3]  25.78 63.37 0 top
Q9  2SK3018  [SOT323_3]  13.97 49.28 0 top
R1  0  [0402_CC]  18.92 8.26 0 top
R2  0  [0402_CC]  18.92 7.24 0 top
R3  3.3K  [RC0402_25]  18.92 9.27 180 top
R4  100K  [0402_CC]  23.88 8.51 0 top
R5  10K  [0402_CC]  18.92 10.79 0 top
R6  1K  [0402_CC]  8.64 17.14 90 top
R7  1K  [0402_CC]  8.89 23.24 270 top
R8  2.2K  [RC0402_25]  26.04 11.05 0 top
R9  3.3K  [RC0402_25]  26.04 12.06 180 top
R10  10K  [0402_CC]  11.94 14.1 90 top
R11  100K  [0402_CC]  10.92 14.1 270 top
R12  0.02  [RC0603_OV]  43.81 27.69 90 top
R13  0.02  [RC0603_OV]  39.5 60.07 90 top
R14  0.02  [RC0603_OV]  43.94 34.42 90 top
R15  220  [RC0603_OV]  72.26 37.47 90 top
R16  0.02  [RC0603_OV]  36.96 49.02 90 top
R17  1K  [0402_CC]  31.37 49.02 0 top
R19  0  [0402_CC]  27.56 59.31 270 top
R20  1.5K  [0402_CC]  27.56 57.78 270 top
R21  0  [0402_CC]  28.83 53.98 270 top
R22  1K  [0402_CC]  29.84 53.98 90 top
R25  0  [0402_CC]  28.57 57.78 90 top
R26  100K  [0402_CC]  30.86 53.98 90 top
R28  10K  [0402_CC]  20.19 58.29 90 top
R29  0  [0402_CC]  21.21 58.29 270 top
R30  1M  [0402_CC]  43.94 39.62 270 top
R31  2.2M  [RC0402_25]  43.94 41.4 90 top
R32  464K  [0402_CC]  24.64 45.97 180 top
R33  30K  [RC0402_25]  45.21 58.67 90 top
R34  200K  [0402_CC]  22.99 45.97 180 top
R35  0  [0402_CC]  37.85 28.07 270 top
R36  0  [0402_CC]  29.59 45.59 0 top
R37  0  [0402_CC]  31.37 45.59 180 top
R38  0  [0402_CC]  22.48 26.16 90 top
R39  100K  [0402_CC]  20.19 31.75 90 top
R40  180K  [0402_CC]  23.62 35.05 180 top
R41  10K  [0402_CC]  19.05 32.77 270 top
R42  40.2K  [0402_CC]  22.1 35.05 180 top
R43  0  [0402_CC]  18.03 32.77 270 top
R44  0  [0402_CC]  49.66 65.66 0 top
R45  0  [0402_CC]  36.96 34.54 270 top
R46  0  [0402_CC]  20.57 36.07 270 top
R47  0  [0402_CC]  51.31 65.66 180 top
R49  0  [0402_CC]  37.97 34.54 270 top
R50  100  [0402_CC]  21.59 40.64 0 top
R51  464K  [0402_CC]  24 64.52 270 top
R52  243K  [0402_CC]  25.4 65.53 0 top
R53  1M  [0402_CC]  23.75 39.62 0 top
R54  200K  [0402_CC]  24 62.87 270 top
R55  100K  [0402_CC]  25.4 60.96 0 top
R56  0  [0402_CC]  45.72 32.64 90 top
R57  10K  [0402_CC]  72.01 39.75 0 top
R58  10K  [0402_CC]  41.78 52.96 270 top
R59  10K  [0402_CC]  42.8 52.96 270 top
R60  0  [0402_CC]  40.13 54.99 270 top
R61  0  [0402_CC]  11.56 44.45 0 top
R62  0  [0402_CC]  10.79 54.1 180 top
R63  0  [0402_CC]  11.56 43.43 0 top
R64  100K  [0402_CC]  11.81 47.88 180 top
R65  0  [0402_CC]  11.81 46.86 180 top
R66  100K  [0402_CC]  12.19 50.29 90 top
R67  100K  [RC0402_25]  10.41 47.37 270 top
R68  0  [0402_CC]  7.75 42.04 0 top
R69  0  [0402_CC]  13.21 51.82 270 top
R70  10K  [0402_CC]  12.19 51.82 90 top
R71  0  [0402_CC]  42.93 69.85 90 top
R72  0  [0402_CC]  52.96 67.94 0 top
R73  10K  [0402_CC]  52.58 70.36 90 top
R74  0  [0402_CC]  53.98 70.36 90 top
R75  100K  [0402_CC]  52.96 71.75 0 top
R76  0  [0402_CC]  48.26 76.83 90 top
R77  62.0  [0805_CC]  49.53 81.03 0 top
R78  62.0  [0805_CC]  45.97 81.03 0 top
R79  0  [0402_CC]  47.24 76.83 90 top
R80  0  [0402_CC]  61.21 32.38 180 top
R81  100K  [0402_CC]  58.55 8 180 top
R82  0  [0402_CC]  54.23 19.43 0 top
R83  0  [0402_CC]  55.5 32.38 270 top
R84  0  [0402_CC]  58.55 9.02 180 top
R85  0  [0402_CC]  57.53 32.38 270 top
R86  10K  [0402_CC]  58.93 19.94 180 top
R87  0  [0402_CC]  58.55 32.38 270 top
R88  0  [0402_CC]  54.48 32.38 270 top
R89  0  [0402_CC]  56.52 32.38 270 top
R90  0  [0402_CC]  59.56 32.38 270 top
R91  10K  [0402_CC]  57.28 19.94 180 top
R92  4.7K  [RC0402_25]  53.34 32.38 270 top
R93  4.7K  [RC0402_25]  51.56 32.38 270 top
R94  0  [0402_CC]  62.74 27.3 90 top
R95  1K  [0402_CC]  71.88 22.73 90 top
R96  1K  [0402_CC]  70.87 23.24 270 top
R97  1K  [0402_CC]  65.79 26.67 270 top
R98  0  [0402_CC]  69.85 21.72 90 top
R99  10K  [0402_CC]  69.34 22.99 180 top
R100  1K  [0402_CC]  65.79 24.89 270 top
R101  0  [0402_CC]  68.83 21.72 90 top
R102  1K  [0402_CC]  67.82 23.37 90 top
R103  1K  [0402_CC]  67.82 24.89 270 top
R104  0  [0402_CC]  51.18 28.19 180 top
R105  0  [0402_CC]  51.18 21.59 180 top
R106  0  [0402_CC]  51.18 27.18 180 top
R107  0  [0402_CC]  51.18 20.57 180 top
R108  49.9  [RC0603_OV]  92.08 22.73 270 top
R109  49.9  [RC0603_OV]  92.08 19.94 90 top
R110  49.9  [RC0603_OV]  92.08 17.27 270 top
R111  49.9  [RC0603_OV]  92.08 14.48 90 top
R113  1K  [0402_CC]  89.03 24.13 270 top
R114  1K  [0402_CC]  88.01 24.13 270 top
R115  1K  [0402_CC]  79.38 16.64 90 top
R116  0  [0402_CC]  84.45 11.3 90 top
R117  6.49K  [0402_CC]  90.04 24.13 90 top
R118  10K  [0402_CC]  85.47 11.3 270 top
R119  4.7K  [0402_CC]  87 24.13 90 top
R120  1K  [0402_CC]  84.96 24.13 90 top
R121  1K  [0402_CC]  82.04 24.13 90 top
R122  1K  [0402_CC]  85.98 24.13 90 top
R123  4.7K  [RC0402_25]  83.95 24.13 90 top
R124  4.7K  [0402_CC]  83.06 24.13 90 top
R125  1K  [0402_CC]  79.38 11.3 270 top
R126  1K  [0402_CC]  80.39 11.3 270 top
R127  1K  [0402_CC]  79.38 21.84 90 top
R128  4.7K  [RC0402_25]  78.36 11.3 270 top
R129  4.7K  [0402_CC]  81.41 11.3 270 top
R130  4.7K  [0402_CC]  80.39 21.84 90 top
R131  1K  [0402_CC]  80.39 18.41 90 top
R132  4.7K  [RC0402_25]  79.38 18.41 90 top
R133  1K  [0402_CC]  82.42 11.3 270 top
R134  1K  [0402_CC]  83.44 11.3 270 top
R135  1K  [0402_CC]  80.77 24.13 90 top
R136  4.7K  [0402_CC]  79.38 20.32 90 top
R137  1K  [0402_CC]  80.39 16.64 270 top
R138  0  [0402_CC]  39.75 53.59 270 top
R139  10K  [0402_CC]  24.38 68.83 0 top
R140  10K  [0402_CC]  30.1 72.64 90 top
R141  10K  [0402_CC]  26.04 68.83 0 top
R142  0  [0402_CC]  59.44 70.48 0 bottom
R143  10K  [0402_CC]  69.34 69.22 270 top
R144  10K  [0402_CC]  110.74 45.85 270 top
R145  10K  [0402_CC]  112.9 45.85 0 top
R146  10K  [0402_CC]  123.44 45.85 270 top
R147  10K  [0402_CC]  124.08 34.42 180 top
R148  10K  [0402_CC]  127 34.42 180 top
R149  100  [0402_CC]  131.06 45.85 270 top
R150  10K  [0402_CC]  120.9 45.85 90 top
R151  10K  [0402_CC]  118.36 45.85 90 top
R152  10K  [0402_CC]  108.2 45.85 90 top
R153  0  [0402_CC]  67.18 34.04 180 top
R154  0  [0402_CC]  68.71 34.29 180 top
R155  0  [0402_CC]  82.42 25.81 180 top
R156  0  [0402_CC]  68.71 35.18 180 top
R157  0  [0402_CC]  66.42 74.93 180 top
R158  0  [0402_CC]  64.64 74.93 180 top
R159  0  [0402_CC]  62.87 74.93 180 top
R160  0  [0402_CC]  80.14 34.8 180 top
R161  0  [0402_CC]  61.09 75.18 180 top
R162  0  [0402_CC]  80.14 33.66 180 top
R163  0  [0402_CC]  59.44 75.56 180 top
R164  0  [0402_CC]  97.54 25.15 270 top
R165  0  [0402_CC]  57.78 75.56 180 top
R166  0  [0402_CC]  98.55 25.15 270 top
R167  0  [0402_CC]  74.68 35.31 180 top
R168  0  [0402_CC]  84.84 14.48 180 bottom
R169  0  [0402_CC]  82.3 20.45 180 bottom
R170  0  [0402_CC]  82.3 19.43 180 bottom
R171  0  [0402_CC]  83.82 18.8 270 bottom
R172  0  [0402_CC]  84.96 21.72 180 bottom
R173  0  [0402_CC]  121.35 31.54 90 top
R174  0  [0402_CC]  123.89 31.54 90 top
R176  100K  [0402_CC]  91.95 58.67 180 bottom
R177  0  [0402_CC]  71.5 48.21 0 top
R178  100K  [0402_CC]  94.36 49.53 90 bottom
R179  180K  [RC0402_25]  118.75 65.41 0 top
R180  10K  [0402_CC]  117.73 60.71 0 top
R181  0  [0402_CC]  121.16 81.41 270 top
R182  10K  [0402_CC]  117.09 73.91 0 top
R183  4.7K  [RC0402_25]  121.54 62.61 270 top
R184  0  [0402_CC]  118.62 73.91 0 top
R185  10K  [0402_CC]  121.41 68.07 90 top
R186  1K  [0402_CC]  116.33 63.37 180 top
R187  0  [0402_CC]  121.41 69.6 90 top
R188  0  [0402_CC]  116.2 57.4 180 top
R189  33  [RC0402_25]  123.95 81.53 270 top
R190  33  [RC0402_25]  123.06 81.53 270 top
R191  0  [0402_CC]  116.2 58.42 180 top
R192  10K  [0402_CC]  127.76 65.41 90 top
R193  10K  [0402_CC]  135.64 62.74 0 top
R194  4.7K  [RC0402_25]  135.64 63.63 180 top
R195  4.7K  [RC0402_25]  118.87 67.94 90 top
R196  10K  [0402_CC]  119.89 68.07 270 top
R197  10K  [0402_CC]  127.76 61.47 270 top
R198  220  [RC0603_OV]  128.4 75.69 0 top
R199  0  [0402_CC]  135 53.72 90 top
R200  4.7K  [0402_CC]  128.91 78.61 270 top
R201  10K  [0402_CC]  136.02 53.72 270 top
R202  4.7K  [RC0402_25]  137.03 53.72 90 top
R203  10K  [0402_CC]  129.92 78.61 90 top
R204  0  [0402_CC]  135 49.02 90 top
R205  10K  [0402_CC]  136.02 49.02 270 top
R206  4.7K  [RC0402_25]  137.03 49.02 90 top
R207  10K  [0402_CC]  112.39 86.49 180 top
R208  0  [0402_CC]  132.46 70.87 270 top
R209  10K  [0402_CC]  133.35 77.34 270 top
R210  0  [0402_CC]  133.48 70.87 270 top
R211  100K  [RC0402_25]  134.37 77.34 90 top
R212  10K  [0402_CC]  131.32 75.82 90 top
R213  15K  [RC0402_25]  132.33 75.69 270 top
R214  1K  [0402_CC]  131.32 77.34 270 top
R239  0  [0402_CC]  55.63 85.72 0 top
R240  10K  [0402_CC]  66.8 79.38 0 top
R241  10K  [0402_CC]  66.8 84.45 0 top
R242  0  [0402_CC]  66.8 83.44 0 top
R243  0  [0402_CC]  66.8 80.39 0 top
R244  10K  [0402_CC]  60.58 87.63 90 top
R245  10K  [0402_CC]  66.8 81.41 180 top
R246  0  [0402_CC]  66.8 82.42 0 top
R247  10K  [0402_CC]  61.09 78.23 90 top
R248  0  [0402_CC]  62.1 78.23 270 top
R249  4.7K  [RC0402_25]  55.63 81.15 180 top
R250  4.7K  [RC0402_25]  58.93 78.23 270 top
R251  0  [0402_CC]  55.63 82.3 180 top
R252  0  [0402_CC]  60.07 78.23 270 top
R253  47K  [RC0402_25]  87.63 54.48 90 bottom
R254  47K  [RC0402_25]  88.77 58.55 270 bottom
R255  47K  [RC0402_25]  93.34 49.53 270 bottom
R256  47K  [RC0402_25]  90.68 49.53 270 bottom
R257  47K  [RC0402_25]  89.79 49.53 270 bottom
R258  47K  [RC0402_25]  87.12 49.53 270 bottom
R259  47K  [RC0402_25]  87.63 52.2 90 bottom
R260  47K  [RC0402_25]  84.96 49.53 270 bottom
R261  47K  [RC0402_25]  82.42 49.53 270 bottom
R262  47K  [RC0402_25]  84.07 49.53 90 bottom
R263  47K  [RC0402_25]  81.53 61.72 90 top
R264  47K  [RC0402_25]  90.04 58.55 270 bottom
R265  1K  [RC0402_25]  97.41 56.26 180 bottom
R266  1K  [RC0402_25]  97.41 54.99 180 bottom
R267  1K  [RC0402_25]  97.41 53.72 180 bottom
R268  1K  [RC0402_25]  97.41 52.45 180 bottom
R269  1K  [RC0402_25]  92.46 49.53 270 bottom
R270  1K  [RC0402_25]  91.57 49.53 270 bottom
R271  1K  [RC0402_25]  85.85 49.53 270 bottom
R272  0  [0402_CC]  74.68 70.74 180 top
R273  0  [0402_CC]  76.45 70.1 180 top
R274  0  [0402_CC]  78.36 69.72 180 top
R275  0  [0402_CC]  80.26 69.34 180 top
R276  0  [0402_CC]  82.42 68.96 180 top
R277  0  [0402_CC]  84.07 68.58 180 top
R278  0  [0402_CC]  85.98 68.2 180 top
R279  0  [0402_CC]  87.88 67.94 180 top
R280  0  [0402_CC]  86.74 40.64 180 top
R281  0  [0402_CC]  88.65 40.26 180 top
R282  0  [0402_CC]  90.55 39.88 180 top
R283  0  [0402_CC]  84.84 43.05 180 top
R284  0  [0402_CC]  87 42.67 180 top
R285  0  [0402_CC]  80.9 42.29 180 top
R286  0  [0402_CC]  82.8 41.4 180 top
R287  0  [0402_CC]  85.09 41.02 180 top
R288  0  [0402_CC]  73.53 54.74 0 top
R289  0  [0402_CC]  73.53 53.72 0 top
R290  0  [0402_CC]  71.12 52.83 0 top
R291  0  [0402_CC]  71.25 61.09 0 top
R293  0  [0402_CC]  71.25 60.2 0 top
R294  0  [0402_CC]  73.53 51.94 0 top
R295  0  [0402_CC]  71.12 51.94 0 top
R296  0  [0402_CC]  73.53 50.93 0 top
R297  0  [0402_CC]  71.25 59.18 0 top
R298  0  [0402_CC]  73.53 49.78 0 top
R299  0  [0402_CC]  71.25 58.29 0 top
R300  0  [0402_CC]  71.25 57.4 0 top
R301  0  [0402_CC]  73.53 57.78 0 top
R302  0  [0402_CC]  73.53 56.77 0 top
R303  0  [0402_CC]  73.53 55.75 0 top
R304  0  [0402_CC]  66.55 62.87 0 top
R306  0  [0402_CC]  73.53 48.77 0 top
R307  0  [0402_CC]  66.55 61.85 0 top
R308  0  [0402_CC]  68.83 61.72 0 top
R309  0  [0402_CC]  84.84 44.07 0 top
R310  0  [0402_CC]  89.79 67.31 0 top
R311  0  [0402_CC]  68.83 60.83 0 top
R312  0  [0402_CC]  8 46.99 270 top
R313  33K  [RC0402_25]  61.59 69.47 0 bottom
R314  1K  [RC0402_25]  88.9 49.53 270 bottom
R315  1K  [RC0402_25]  88.01 49.53 270 bottom
R316  0  [0402_CC]  45.85 49.78 180 bottom
R357  0.02  [RC0603_OV]  34.8 75.82 0 top
R358  0  [0402_CC]  22.73 68.83 0 top
R359  0  [0402_CC]  24.38 67.82 180 top
R360  0  [0402_CC]  28.57 62.74 90 top
R361  0  [0402_CC]  29.59 64.77 90 top
R362  0  [0402_CC]  30.61 62.74 90 top
R363  0  [0402_CC]  33.4 62.61 90 top
R364  0  [0402_CC]  33.15 67.56 90 top
SW1  EG2209A  [SW6_DPDT_11X6MM]  18.29 19.81 0 top
SW2  SPST PB  [SW4_PB_ESW_SM_P177]  4.95 74.8 180 top
SW3  SPST PB  [SW4_PB_ESW_SM_P177]  4.95 31.24 180 top
SW4  SPST PB  [SW4_PB_ESW_SM_P177]  4.95 60.58 180 top
SW5  SPST PB  [SW4_PB_ESW_SM_P177]  95 84.71 90 top
SW8  DHN-04  [97C04]  92.08 54.36 90 bottom
TP1  -  [TPAD_030]  15.88 6.73 0 top
TP2  5006  [TP_TH_063]  136.53 80.14 0 top
TP3  5006  [TP_TH_063]  3.81 21.72 0 top
TP4  5006  [TP_TH_063]  134.37 27.69 0 top
TP5  5006  [TP_TH_063]  10.16 85.34 0 top
TP6  TP_35MIL  [TESTPOINT_35MIL]  44.45 50.67 0 top
TP7  TP_35MIL  [TESTPOINT_35MIL]  45.34 37.47 0 top
TP8  TP_35MIL  [TESTPOINT_35MIL]  25.02 33.78 90 top
TP9  TP_35MIL  [TESTPOINT_35MIL]  17.91 29.97 90 top
TP10  TP_35MIL  [TESTPOINT_35MIL]  24.38 66.29 0 top
TP11  TP_35MIL  [TESTPOINT_35MIL]  54.36 63.75 0 top
TP12  TP_35MIL  [TESTPOINT_35MIL]  55.37 64.77 0 top
TP13  TP_35MIL  [TESTPOINT_35MIL]  44.83 42.55 0 top
TP14  TP_35MIL  [TESTPOINT_35MIL]  80.52 19.94 0 top
TP15  TP_35MIL  [TESTPOINT_35MIL]  81.66 14.99 0 top
TP16  TP_35MIL  [TESTPOINT_35MIL]  90.04 22.23 0 top
TP17  -  [TPAD_030]  119.38 60.58 0 top
TP18  -  [TPAD_030]  120.52 65.91 0 top
TP19  -  [TPAD_030]  119.76 83.31 90 top
TP20  -  [TPAD_030]  118.11 81.15 90 top
TP21  -  [TPAD_030]  119.76 81.15 90 top
TP22  -  [TPAD_030]  125.09 69.47 90 top
TP23  -  [TPAD_030]  125.09 71.25 90 top
TP24  -  [TPAD_030]  117.35 68.2 90 top
TP25  TP_35MIL  [TESTPOINT_35MIL]  45.47 49.78 0 top
TVS1  ESD5B5.0ST1G  [DIODE2_SOD523]  36.83 7.62 180 top
TVS2  ESD5B5.0ST1G  [DIODE2_SOD523]  43.69 11.68 0 top
TVS3  ESD5B5.0ST1G  [DIODE2_SOD523]  58.55 6.73 180 top
TVS4  ESD5B5.0ST1G  [DIODE2_SOD523]  58.55 11.68 180 top
TVS5  ESD5B5.0ST1G  [DIODE2_SOD523]  58.55 4.57 180 top
U1  PIMXRT1021DAG5A  [LQFP144_0P5_20X20MM]  57.91 48.64 270 top
U2  UM803RS  [SOT-23]  26.54 54.61 0 top
U3  UM1750S-00  [SOT23-5_A]  21.97 48.51 0 top
U4  MP2144GJ  [TSOT23_8_0P65_2X1]  22.73 31.5 90 top
U5  UM805RE  [SOT_143]  18.16 36.07 0 top
U6  UM1750S-00  [SOT23-5_A]  21.08 64.14 0 top
U7  NX5P3090UK  [WLCSP12_0P4_1P38X1P68MM_SMDP]  9.4 50.16 270 top
U8  RClamp0854P.TCT  [SLP1616P6]  7.87 43.81 270 top
U9  TJA1057GT/3  [SO8_1P27_4X5]  47.75 70.87 0 top
U10  WM8960  [QFN32_S142EP]  56.52 26.8 180 top
U11  KSZ8081RNB  [QFN32_0P5_EP3P3]  85.85 18.16 180 top
U12  SRV05-4  [SOT23_S6]  104.27 15.24 0 top
U13  IS25LP064A-JBLE  [SO8_W]  63.5 70.48 180 top
U14  IS42S16160J-6TLI  [TSOPII_54]  93.85 55.24 270 top
U15  NTSX2102GU8H  [XQFN8_1P45X1P25MM]  119.25 63.12 0 top
U16  MK20DX128VFM5  [QFN32_S142EP]  122.94 76.07 270 top
U17  NLX2G14  [UDFN6_1P45X1_0P5MM]  123.32 68.83 0 top
U18  0402ESDA-MLP  [0402_MLP]  127.89 83.31 0 top
U19  0402ESDA-MLP  [0402_MLP]  122.05 83.31 180 top
U20  0402ESDA-MLP  [0402_MLP]  124.97 83.31 0 top
U21  74LVCH1T45GS  [SOT1202_0P35_1P05X1P05]  136.14 65.41 180 top
U22  74LVC2T45GS  [SON8_0P35_1P05X1P45]  136.14 60.2 180 top
U23  74LVCH1T45GS  [SOT1202_0P35_1P05X1P05]  136.14 56.01 180 top
U24  74LVCH1T45GS  [SOT1202_0P35_1P05X1P05]  136.14 51.31 180 top
U25  NX5P3090UK  [WLCSP12_0P4_1P38X1P68MM_SMDP]  134.24 73.53 0 top
U26  FXOS8700CQ  [QFN5X3_0P5_3X3]  61.09 82.93 0 top
U27  NX3P191UK  [WLCSP4_0P4_0P8X0P8_SMDP]  22.99 58.04 270 top
Y2  32.768KHZ  [XTAL2-3P2X1P5-SM]  41.4 46.86 270 top
Y3  8.00MHZ  [XTAL3_3P35X1P45_SM]  116.97 71.25 270 top
Y4  24MHz  [XTL4_2P1X1P7MM_SM]  40.51 39.62 90 top

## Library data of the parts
C1-C4 C6-C26 C28-C33 C35-C43 C46-C80 C82 C83 C85-C88 C90-C129 C134-C139 C142-C159 C162-C165 C167-C180 = CAP_NP
C5 C81 C84 C89 C166 = CAP_NP: tolerance: 20%
C44 C45 C140 C141 = CAP_NP: room: ATLAS-AP
C130-C133 C160 C161 = CAP_NP: tolerance: 5%
D1 = ZDIODE
D2 D4 D6-D10 D12-D14 = DIODE_SCHTKY
D3 = LED_DUAL_SEP_RG
D5 D15 D16 = LED
D11 = DIODE_NUP2105L
FL1 = FILTER_4P
H1-H4 = SPACER
J1 J29 = CONN_HDR_5X2
J2 = PHONEJACK-3
J3-J8 J12 J13 J21 J24-J28 J37 = CONN_HDR_2X1
J9 J23 = USB_MINI_AB_RECEPTACLE
J10 J22 = CONN_HDR_3X1
J11 = CONN_AUDIOJACK_6P
J14 = RJ45_HR961160C_12P
J15 = CON8_SDCARD_DETECT
J16 = CONN_HDR_10X2
J17 J20 = CONN_HDR_8X1
J18 = CONN_HDR_6X1
J19 = CONN_HDR_10X1
JP1 = JUMPER1x2
L1 = IND_FERRITE
L2 = IND: tolerance: 30%
L3 L10-L12 = BEAD: tolerance: 25%
L4 = DLW43
L5 = BEAD: tolerance: 25%; signal model: DLW43_IND4_CHOKE_0805_DISCRETE__90OHM
L6 L7 L9 L13 L20 = INDUCTOR_FERRITE
L8 = INDUCTOR_FERRITE: signal model: DLW43_IND4_CHOKE_0805_DISCRETE__90OHM
P1 = MIC_POM
Q1 Q2 = FDMA530PZ
Q3 = PNP
Q4 = NMOS_2N7002BKW_3P
Q8 Q9 = 2SK3018
R1 R2 R6 R7 R15 R17 R19-R22 R25 R26 R29-R47 R49-R56 R60 R62 R65 R67 R68 R70-R74 R77 R78 R80-R82 R84 R86 R92-R98 R100-R103 R113-R115 R117 R119-R122 R124-R127 R129-R131 R133-R137 R140 R142 R144-R152 R159-R174 R176 R178 R181 R184 R186-R188 R191 R192 R197 R199 R200 R203 R204 R208 R210-R212 R214 R239-R271 R312-R316 R358 R359 = RES
R3-R5 R8-R11 R28 R57-R59 R64 R66 R75 R99 R118 R123 R128 R132 R139 R141 R143 R180 R182 R183 R185 R193-R196 R198 R201 R202 R205-R207 R209 = RES: tolerance: 5%
R12-R14 R16 R108-R111 R179 R189 R190 R213 R357 = RES: tolerance: 1%
R61 R63 R69 R76 R79 R83 R85 R87-R91 R104-R107 R116 R138 = RES: signal model: RES_0402_CC_DISCRETE_0.45_MM_47_0
R153-R158 R177 R272-R291 R293-R304 R306-R311 R360-R364 = RES: signal model: RES_0402_CC_DISCRETE_0_0
SW1 = SW_DPDT_3
SW2-SW5 = SW_PB_ESW
SW8 = SW_DIP-4_SM
TP1 TP17-TP24 = TestLoop
TP2-TP5 = TEST_POINT
TP6-TP16 TP25 = T POINT R: Tolerance: TOLERANCE; User Part Number: 510-75618
TVS1-TVS5 U18-U20 = DIODE_TVS_BIDIR
U1 = IMXRT1020_LQFP144P
U2 = SGM803_SOT23-3P
U3 U6 = UM1750S-00_5P
U4 = MP2144GJ_TSOT23_8P
U5 = UM805_4P
U7 U25 = NX5P3090UK_WLCSP12
U8 = RCLAMP1654P_NEW
U9 = TJA1057GT3_8P
U10 = WM8960_QFN_33P
U11 = KSZ8081RNB_32P
U12 = SRV05-4
U13 = IS25LP064A_8P
U14 = MT48LC16M16A2P_54P
U15 = NTSX2102GU8H_8P
U16 = PK20DX128V_QFN_32P
U17 = NLX2G14_6P
U21 U23 U24 = 74LVCH1T45_6P
U22 = 74LVC2T45DC_8P
U26 = FXOS8700CQ_QFN_16P
U27 = ADP172_CSP_4P
Y2 = CRYSTAL
Y3 = XTAL_CS
Y4 = XTAL_13

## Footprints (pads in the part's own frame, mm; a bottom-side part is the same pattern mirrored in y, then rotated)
97C04
  rect 0.762x1.245 smd: 1(-1.905,-3.073) 2(-0.635,-3.073) 3(0.635,-3.073) 4(1.905,-3.073) 5(1.905,3.073) 6(0.635,3.073) 7(-0.635,3.073) 8(-1.905,3.073)
100MIL_TH
  rect 1.422x1.422 hole 0.914: 1(0,0)
  round 1.422 hole 0.914: 2(2.54,0)
0402_CC
  rect 0.457x0.508 smd: 1(-0.375,0) 2(0.375,0)
0402_MLP
  rect 0.9x0.7 smd: 1(-0.65,0) 2(0.65,0)
0603_CC
  rect 0.711x0.838 smd: 1(-0.65,0) 2(0.65,0)
0805_CC
  rect 0.94x1.346 smd: 1(-0.78,0) 2(0.78,0)
CC0402_25
  round 0.635 smd: 1(-0.508,0) 2(0.508,0)
CC0603_OV
  oval 0.889x1.143 smd: 1(-0.762,0) 2(0.762,0)
CC1206_OV
  oval 1.016x1.778 smd: 1(-1.524,0) 2(1.524,0)
CC1210
  rect 1.778x2.845 smd: 1(-1.397,0) 2(1.397,0)
CON3_PWR_TH
  oval 4.013x1.549 hole 3.5x0.8: 1(0,0)
  oval 3.759x1.549 hole 2.997x0.787: 2(0,-6)
  oval 1.549x3.759 hole 0.787x2.997: 3(4.8,-2.5)
CON6_AUDJACK_RA_TH
  round 0.254 hole 1.499 unplated: (0.4,2.7) (7.4,2.7)
  oval 2.108x1.092 hole 1.499x0.508: 1(0,0) 4(0,5.1)
  rect 1.6x2.007 smd: 2(9.4,6.1) 3(9.4,-0.7) 5(6.3,6.1) 6(6.3,-0.7)
CON12_RJ45_1P02_SM
  round 0.254 hole 2.997 unplated: (-6.35,9.96) (6.35,9.96)
  rect 0.813x4.597 smd: 1(-6.61,-9.96) 2(-4.77,-9.96) 11(4.77,-9.96) 12(6.61,-9.96)
  rect 0.61x4.597 smd: 3(-3.57,-9.96) 4(-2.55,-9.96) 5(-1.53,-9.96) 6(-0.51,-9.96) 7(0.51,-9.96) 8(1.53,-9.96) 9(2.55,-9.96) 10(3.57,-9.96)
  custom 0.75x0.75 smd: 13(-8.92,9.96) 14(8.92,9.96)
CON_SDCARD_95220
  rect 0.813x1.499 smd: 1(-1.94,3.267) 2(-0.84,2.867) 3(0.26,3.267) 4(1.36,3.468) 5(2.46,3.267) 6(3.56,3.468) 7(4.66,3.267) 8(5.76,3.267)
  rect 0.991x0.94 smd: 9(3.56,-7.368)
  rect 1.397x1.905 smd: SH1(6.6,6.187) SH2(-6.6,7.107)
  rect 1.295x1.422 smd: SH3(4.95,-7.092) SH4(-0.75,-7.092)
CON_SKT1X6_TH
  rect 1.524x1.524 hole 1.041: 1(0,0)
  round 1.524 hole 1.041: 2(0,-2.54) 3(0,-5.08) 4(0,-7.62) 5(0,-10.16) 6(0,-12.7)
CON_SKT1X8_TH
  rect 1.651x1.651 hole 1.016: 1(0,0)
  round 1.651 hole 1.016: 2(0,-2.54) 3(0,-5.08) 4(0,-7.62) 5(0,-10.16) 6(0,-12.7) 7(0,-15.24) 8(0,-17.78)
CON_SKT1X10_TH
  rect 1.651x1.651 hole 1.016: 1(0,0)
  round 1.651 hole 1.016: 2(0,-2.54) 3(0,-5.08) 4(0,-7.62) 5(0,-10.16) 6(0,-12.7) 7(0,-15.24) 8(0,-17.78) 9(0,-20.32) 10(0,-22.86)
CON_USB5_MICROAB_0P65_SM
  round 0.254 hole 0.559 unplated: (-2,2.115) (2,2.115)
  rect 0.406x1.346 smd: 1(-1.3,2.64) 2(-0.65,2.64) 3(0,2.64) 4(0.65,2.64) 5(1.3,2.64)
  rect 1.905x1.905 smd: S1(-3.95,-0.035) S2(3.95,-0.035) S3(-1.2,-0.035) S4(1.2,-0.035)
DIODE2_SOD523
  rect 0.61x0.813 smd: 1(-0.85,0) 2(0.85,0)
HDR102
  rect 1.524x1.524 hole 1.016: 1(0,0)
  round 1.524 hole 1.016: 2(0,-2.54)
HDR103
  rect 1.524x1.524 hole 1.016: 1(0,0)
  round 1.524 hole 1.016: 2(0,-2.54) 3(0,-5.08)
HDR205
  rect 1.676x1.676 hole 1.016: 1(0,0)
  round 1.676 hole 1.016: 2(2.54,0) 3(0,-2.54) 4(2.54,-2.54) 5(0,-5.08) 6(2.54,-5.08) 7(0,-7.62) 8(2.54,-7.62) 9(0,-10.16) 10(2.54,-10.16)
HDR205_50_TH
  rect 1.016x1.016 hole 0.66: 1(0,0)
  round 1.016 hole 0.66: 2(0,1.27) 3(1.27,0) 4(1.27,1.27) 5(2.54,0) 6(2.54,1.27) 7(3.81,0) 8(3.81,1.27) 9(5.08,0) 10(5.08,1.27)
HDR_2X10M_100_TH
  rect 1.778x1.778 hole 1.143: 1(0,0)
  round 1.778 hole 1.143: 2(2.54,0) 3(0,-2.54) 4(2.54,-2.54) 5(0,-5.08) 6(2.54,-5.08) 7(0,-7.62) 8(2.54,-7.62) 9(0,-10.16) 10(2.54,-10.16) 11(0,-12.7) 12(2.54,-12.7) 13(0,-15.24) 14(2.54,-15.24) 15(0,-17.78) 16(2.54,-17.78) 17(0,-20.32) 18(2.54,-20.32) 19(0,-22.86) 20(2.54,-22.86)
IND4_4P7X3P4_SMT
  rect 1.372x0.914 smd: 1(-2.275,1.25) 2(-2.275,-1.25) 3(2.275,-1.25) 4(2.275,1.25)
IND4_CHOKE_0805
  rect 0.914x0.406 smd: 1(-0.85,-0.4) 2(0.85,-0.4) 3(0.85,0.4) 4(-0.85,0.4)
IND_1608
  rect 0.61x0.813 smd: 1(-0.7,0) 2(0.7,0)
IND_4020
  rect 1.118x3.708 smd: 1(-1.5,0) 2(1.5,0)
IND_VLS4012E
  rect 1.549x4.013 smd: 1(-1.475,0) 2(1.475,0)
LED_0603
  rect 0.838x0.787 smd: A(-0.775,0) C(0.775,0)
LED_DUAL_3025MM_SM
  rect 1.702x1.118 smd: 1(-1.35,-0.85) 2(1.35,-0.85) 3(-1.35,0.85) 4(1.35,0.85)
LQFP144_0P5_20X20MM
  rect 1.422x0.279 smd: 1(-10.7,8.75) 2(-10.7,8.25) 3(-10.7,7.75) 4(-10.7,7.25) 5(-10.7,6.75) 6(-10.7,6.25) 7(-10.7,5.75) 8(-10.7,5.25) 9(-10.7,4.75) 10(-10.7,4.25) 11(-10.7,3.75) 12(-10.7,3.25) 13(-10.7,2.75) 14(-10.7,2.25) 15(-10.7,1.75) 16(-10.7,1.25) 17(-10.7,0.75) 18(-10.7,0.25) 19(-10.7,-0.25) 20(-10.7,-0.75) 21(-10.7,-1.25) 22(-10.7,-1.75) 23(-10.7,-2.25) 24(-10.7,-2.75) 25(-10.7,-3.25) 26(-10.7,-3.75) 27(-10.7,-4.25) 28(-10.7,-4.75) 29(-10.7,-5.25) 30(-10.7,-5.75) 31(-10.7,-6.25) 32(-10.7,-6.75) 33(-10.7,-7.25) 34(-10.7,-7.75) 35(-10.7,-8.25) 36(-10.7,-8.75) 73(10.7,-8.75) 74(10.7,-8.25) 75(10.7,-7.75) 76(10.7,-7.25) 77(10.7,-6.75) 78(10.7,-6.25) 79(10.7,-5.75) 80(10.7,-5.25) 81(10.7,-4.75) 82(10.7,-4.25) 83(10.7,-3.75) 84(10.7,-3.25) 85(10.7,-2.75) 86(10.7,-2.25) 87(10.7,-1.75) 88(10.7,-1.25) 89(10.7,-0.75) 90(10.7,-0.25) 91(10.7,0.25) 92(10.7,0.75) 93(10.7,1.25) 94(10.7,1.75) 95(10.7,2.25) 96(10.7,2.75) 97(10.7,3.25) 98(10.7,3.75) 99(10.7,4.25) 100(10.7,4.75) 101(10.7,5.25) 102(10.7,5.75) 103(10.7,6.25) 104(10.7,6.75) 105(10.7,7.25) 106(10.7,7.75) 107(10.7,8.25) 108(10.7,8.75)
  rect 0.279x1.422 smd: 37(-8.75,-10.7) 38(-8.25,-10.7) 39(-7.75,-10.7) 40(-7.25,-10.7) 41(-6.75,-10.7) 42(-6.25,-10.7) 43(-5.75,-10.7) 44(-5.25,-10.7) 45(-4.75,-10.7) 46(-4.25,-10.7) 47(-3.75,-10.7) 48(-3.25,-10.7) 49(-2.75,-10.7) 50(-2.25,-10.7) 51(-1.75,-10.7) 52(-1.25,-10.7) 53(-0.75,-10.7) 54(-0.25,-10.7) 55(0.25,-10.7) 56(0.75,-10.7) 57(1.25,-10.7) 58(1.75,-10.7) 59(2.25,-10.7) 60(2.75,-10.7) 61(3.25,-10.7) 62(3.75,-10.7) 63(4.25,-10.7) 64(4.75,-10.7) 65(5.25,-10.7) 66(5.75,-10.7) 67(6.25,-10.7) 68(6.75,-10.7) 69(7.25,-10.7) 70(7.75,-10.7) 71(8.25,-10.7) 72(8.75,-10.7) 109(8.75,10.7) 110(8.25,10.7) 111(7.75,10.7) 112(7.25,10.7) 113(6.75,10.7) 114(6.25,10.7) 115(5.75,10.7) 116(5.25,10.7) 117(4.75,10.7) 118(4.25,10.7) 119(3.75,10.7) 120(3.25,10.7) 121(2.75,10.7) 122(2.25,10.7) 123(1.75,10.7) 124(1.25,10.7) 125(0.75,10.7) 126(0.25,10.7) 127(-0.25,10.7) 128(-0.75,10.7) 129(-1.25,10.7) 130(-1.75,10.7) 131(-2.25,10.7) 132(-2.75,10.7) 133(-3.25,10.7) 134(-3.75,10.7) 135(-4.25,10.7) 136(-4.75,10.7) 137(-5.25,10.7) 138(-5.75,10.7) 139(-6.25,10.7) 140(-6.75,10.7) 141(-7.25,10.7) 142(-7.75,10.7) 143(-8.25,10.7) 144(-8.75,10.7)
MIC_WM-63PR
  rect 1.27x1.27 hole 0.762: 1(0,0)
  round 1.27 hole 0.762: 2(0,1.9)
MLP6_2X2MM_SLUG
  rect 0.483x0.406 smd: 1(-0.913,0.65) 2(-0.913,0) 3(-0.913,-0.65) 4(0.913,-0.65) 5(0.913,0) 6(0.913,0.65)
  rect 1.016x0.991 smd: 7(0,0.3)
  rect 0.66x0.406 smd: 8(0,-0.65)
QFN5X3_0P5_3X3
  rect 0.813x0.305 smd: 1(-1.275,1) 2(-1.275,0.5) 3(-1.275,0) 4(-1.275,-0.5) 5(-1.275,-1) 9(1.275,-1) 10(1.275,-0.5) 11(1.275,0) 12(1.275,0.5) 13(1.275,1)
  rect 0.305x0.813 smd: 6(-0.5,-1.275) 7(0,-1.275) 8(0.5,-1.275) 14(0.5,1.275) 15(0,1.275) 16(-0.5,1.275)
QFN32_0P5_EP3P3
  oval 0.864x0.279 smd: 1(-2.45,1.75) 8(-2.45,-1.75) 17(2.45,-1.75) 24(2.45,1.75)
  rect 0.864x0.279 smd: 2(-2.45,1.25) 3(-2.45,0.75) 4(-2.45,0.25) 5(-2.45,-0.25) 6(-2.45,-0.75) 7(-2.45,-1.25) 18(2.45,-1.25) 19(2.45,-0.75) 20(2.45,-0.25) 21(2.45,0.25) 22(2.45,0.75) 23(2.45,1.25)
  oval 0.279x0.864 smd: 9(-1.75,-2.45) 16(1.75,-2.45) 25(1.75,2.45) 32(-1.75,2.45)
  rect 0.279x0.864 smd: 10(-1.25,-2.45) 11(-0.75,-2.45) 12(-0.25,-2.45) 13(0.25,-2.45) 14(0.75,-2.45) 15(1.25,-2.45) 26(1.25,2.45) 27(0.75,2.45) 28(0.25,2.45) 29(-0.25,2.45) 30(-0.75,2.45) 31(-1.25,2.45)
  rect 3.302x3.302 smd: 33(0,0)
QFN32_S142EP
  custom 0.07x0.07 smd: 1(-2.4,1.751) 2(-2.4,1.251) 3(-2.4,0.751) 4(-2.4,0.25) 5(-2.4,-0.25) 6(-2.4,-0.751) 7(-2.4,-1.251) 8(-2.4,-1.751) 9(-1.751,-2.4) 10(-1.251,-2.4) 11(-0.751,-2.4) 12(-0.25,-2.4) 13(0.25,-2.4) 14(0.751,-2.4) 15(1.251,-2.4) 16(1.751,-2.4) 17(2.4,-1.751) 18(2.4,-1.251) 19(2.4,-0.751) 20(2.4,-0.25) 21(2.4,0.25) 22(2.4,0.751) 23(2.4,1.251) 24(2.4,1.751) 25(1.751,2.4) 26(1.251,2.4) 27(0.751,2.4) 28(0.25,2.4) 29(-0.25,2.4) 30(-0.751,2.4) 31(-1.251,2.4) 32(-1.751,2.4)
  rect 3.607x3.607 smd: 33(0,0)
RC0402_25
  round 0.635 smd: 1(-0.508,0) 2(0.508,0)
RC0603_OV
  oval 0.889x1.143 smd: 1(-0.762,0) 2(0.762,0)
SLP1616P6
  rect 0.305x0.635 smd: 1(-0.5,-0.76) 2(0,-0.76) 3(0.5,-0.76) 4(0.5,0.76) 5(0,0.76) 6(-0.5,0.76)
  rect 1.295x0.457 smd: 7(0,0)
SO8_1P27_4X5
  rect 1.6x0.61 smd: 1(-2.7,1.905) 2(-2.7,0.635) 3(-2.7,-0.635) 4(-2.7,-1.905) 5(2.7,-1.905) 6(2.7,-0.635) 7(2.7,0.635) 8(2.7,1.905)
SO8_W
  rect 2.032x0.635 smd: 1(-3.632,1.905) 2(-3.632,0.635) 3(-3.632,-0.635) 4(-3.632,-1.905) 5(3.632,-1.905) 6(3.632,-0.635) 7(3.632,0.635) 8(3.632,1.905)
SOD523
  rect 0.61x0.813 smd: A(0.85,0) C(-0.85,0)
SOD-123
  rect 1.321x1.219 smd: A(-1.626,0) C(1.626,0)
SOD_523_1P4
  rect 0.406x0.406 smd: A(0.7,0) C(-0.7,0)
SON8_0P35_1P05X1P45
  rect 0.533x0.203 smd: 1(-0.335,0.525) 2(-0.335,0.175) 3(-0.335,-0.175) 4(-0.335,-0.525) 5(0.335,-0.525) 6(0.335,-0.175) 7(0.335,0.175) 8(0.335,0.525)
SOT23-5_A
  rect 1.016x0.762 smd: 1(-1.3,0.95) 2(-1.3,0) 3(-1.3,-0.95) 4(1.3,-0.95) 5(1.3,0.95)
SOT23_A
  rect 0.787x0.889 smd: 1(-0.94,-1.003) 2(0.94,-1.003) 3(0,1.003)
SOT23_S6
  rect 1.27x0.635 smd: 1(-1.219,0.94) 2(-1.219,0) 3(-1.219,-0.94) 4(1.219,-0.94) 5(1.219,0) 6(1.219,0.94)
SOT323_3
  rect 0.406x0.991 smd: 1(0.65,-1.06) 2(-0.65,-1.06) 3(0,1.06)
SOT1202_0P35_1P05X1P05
  rect 0.508x0.152 smd: 1(-0.35,0.35) 2(-0.35,0) 3(-0.35,-0.35) 4(0.35,-0.35) 5(0.35,0) 6(0.35,0.35)
SOT-23
  rect 1.016x1.397 smd: 1(-0.95,-1.1) 2(0.95,-1.1) 3(0,1.1)
SOT_143
  rect 1.219x1.397 smd: 1(-0.75,-1.1)
  rect 1.016x1.397 smd: 2(0.95,-1.1) 3(0.95,1.1) 4(-0.95,1.1)
SPACER_139T
  round 5.588 hole 3.531: 1(0,0)
SW4_PB_ESW_SM_P177
  rect 1.397x2.794 smd: 1(2.248,4.547) 2(2.248,-4.547) 3(-2.248,4.547) 4(-2.248,-4.547)
SW6_DPDT_11X6MM
  rect 1.143x1.143 hole 0.711: 1(0,0)
  round 1.143 hole 0.711: 2(2,0) 3(4,0) 4(0,-2.5) 5(2,-2.5) 6(4,-2.5)
TESTPOINT_35MIL
  round 0.889 smd: 1(0,0)
TP_TH_063
  round 2.311 hole 1.6: 1(0,0)
TPAD_030
  round 0.762 smd: 1(0,0)
TSOPII_54
  rect 2.134x0.559 smd: 1(-5.793,10.4) 2(-5.793,9.6) 3(-5.793,8.8) 4(-5.793,8) 5(-5.793,7.2) 6(-5.793,6.4) 7(-5.793,5.6) 8(-5.793,4.8) 9(-5.793,4) 10(-5.793,3.2) 11(-5.793,2.4) 12(-5.793,1.6) 13(-5.793,0.8) 14(-5.793,0) 15(-5.793,-0.8) 16(-5.793,-1.6) 17(-5.793,-2.4) 18(-5.793,-3.2) 19(-5.793,-4) 20(-5.793,-4.8) 21(-5.793,-5.6) 22(-5.793,-6.4) 23(-5.793,-7.2) 24(-5.793,-8) 25(-5.793,-8.8) 26(-5.793,-9.6) 27(-5.793,-10.4) 28(5.793,-10.4) 29(5.793,-9.6) 30(5.793,-8.8) 31(5.793,-8) 32(5.793,-7.2) 33(5.793,-6.4) 34(5.793,-5.6) 35(5.793,-4.8) 36(5.793,-4) 37(5.793,-3.2) 38(5.793,-2.4) 39(5.793,-1.6) 40(5.793,-0.8) 41(5.793,0) 42(5.793,0.8) 43(5.793,1.6) 44(5.793,2.4) 45(5.793,3.2) 46(5.793,4) 47(5.793,4.8) 48(5.793,5.6) 49(5.793,6.4) 50(5.793,7.2) 51(5.793,8) 52(5.793,8.8) 53(5.793,9.6) 54(5.793,10.4)
TSOT23_8_0P65_2X1
  rect 1.219x0.432 smd: 1(-1.31,0.975) 2(-1.31,0.325) 3(-1.31,-0.325) 4(-1.31,-0.975) 5(1.31,-0.975) 6(1.31,-0.325) 7(1.31,0.325) 8(1.31,0.975)
UDFN6_1P45X1_0P5MM
  rect 0.508x0.305 smd: 1(-0.354,0.5) 2(-0.354,0) 3(-0.354,-0.5) 4(0.354,-0.5) 5(0.354,0) 6(0.354,0.5)
WLCSP4_0P4_0P8X0P8_SMDP
  round 0.254 smd: A1(-0.2,0.2) A2(0.2,0.2) B1(-0.2,-0.2) B2(0.2,-0.2)
